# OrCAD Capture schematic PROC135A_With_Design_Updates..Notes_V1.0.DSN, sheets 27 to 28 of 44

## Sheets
27 27. XDS110 DEBUGGER: size C; title: XDS110 DEBUGGER
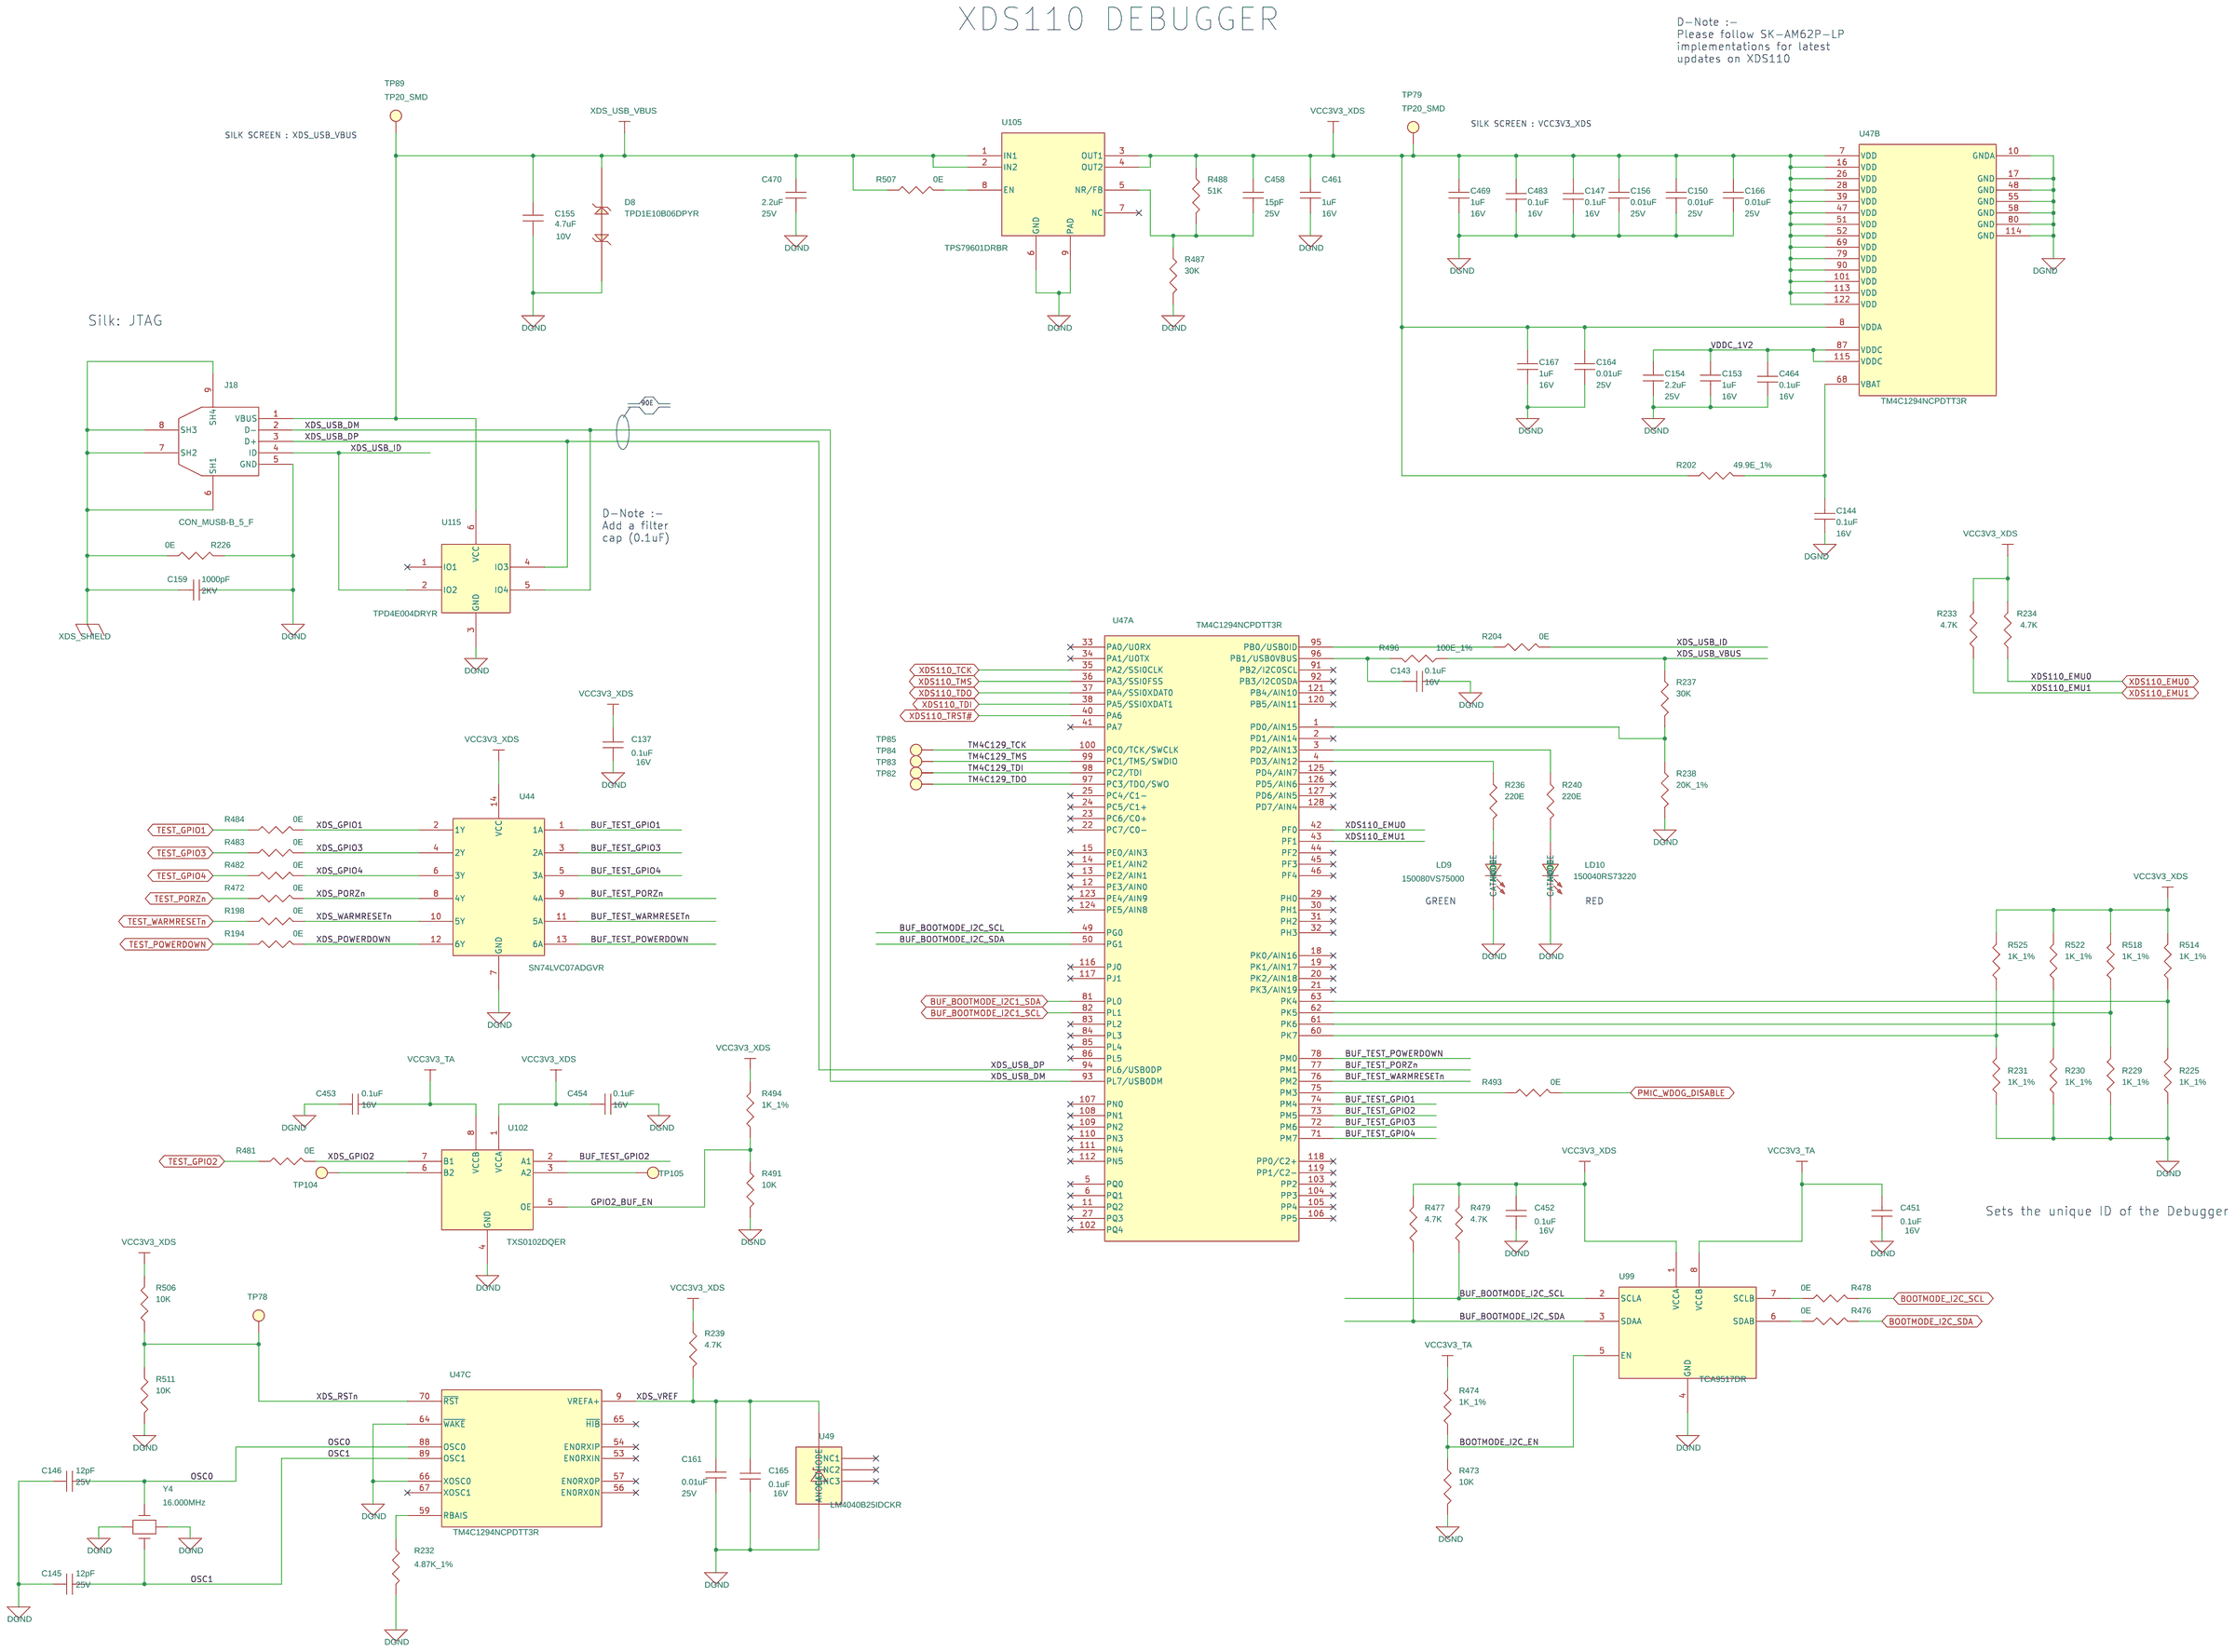
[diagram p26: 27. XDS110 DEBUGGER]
28 28. JTAG BUFFER: size C; title: JTAG BUFFER
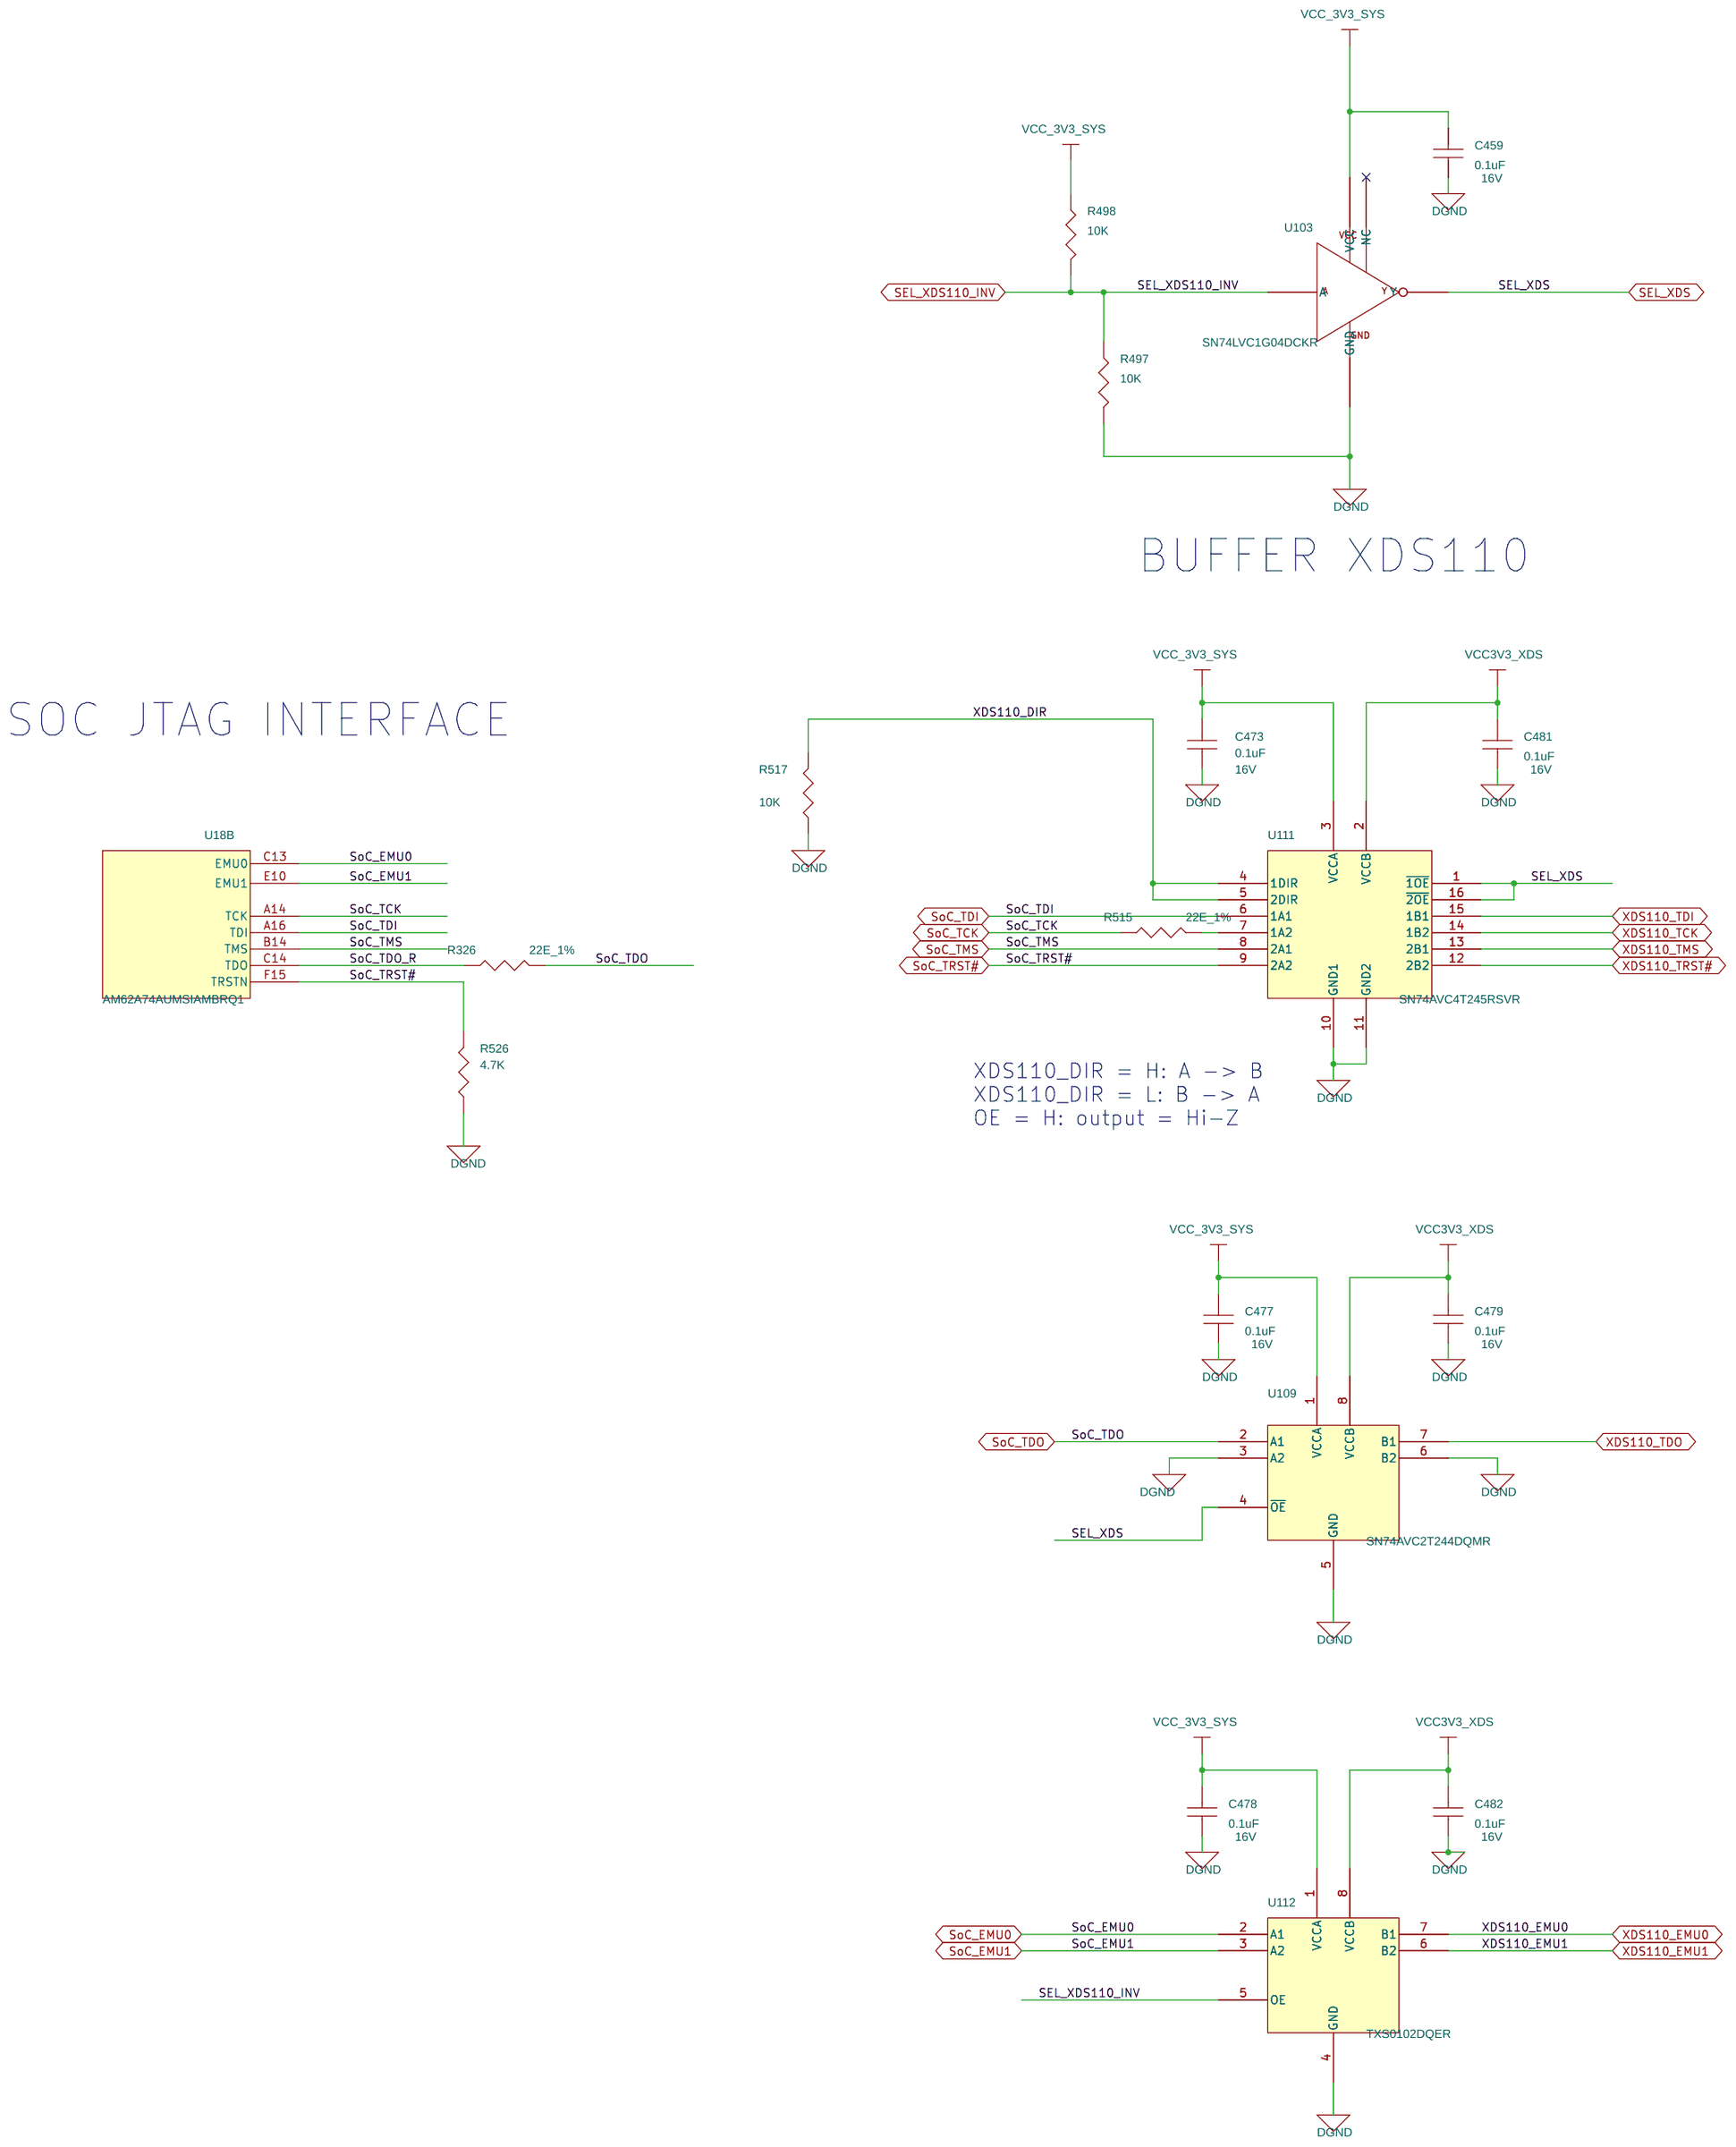
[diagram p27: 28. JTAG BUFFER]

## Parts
sheet 27. XDS110 DEBUGGER
C137  0.1uF  [CAP0201_0-5]
C143  0.1uF  [CAP0201_0-5]
C144  0.1uF  [CAP0201_0-5]
C145  12pF  [CAP0201_0-5]
C146  12pF  [CAP0201_0-5]
C147  0.1uF  [CAP0201_0-5]
C150  0.01uF  [CAP0201_0-5]
C153  1uF  [CAP0201_0-5]
C154  2.2uF  [CAP0402_0-75]
C155  4.7uF  [CAP0402_0-75]
C156  0.01uF  [CAP0201_0-5]
C159  1000pF  [CAP1206_1-75]
C161  0.01uF  [CAP0201_0-5]
C164  0.01uF  [CAP0201_0-5]
C165  0.1uF  [CAP0201_0-5]
C166  0.01uF  [CAP0201_0-5]
C167  1uF  [CAP0201_0-5]
C451  0.1uF  [CAP0201_0-5]
C452  0.1uF  [CAP0201_0-5]
C453  0.1uF  [CAP0201_0-5]
C454  0.1uF  [CAP0201_0-5]
C458  15pF  [CAP0201_0-5]
C461  1uF  [CAP0201_0-5]
C464  0.1uF  [CAP0201_0-5]
C469  1uF  [CAP0201_0-5]
C470  2.2uF  [CAP0402_0-75]
C483  0.1uF  [CAP0201_0-5]
D8  TPD1E10B06DPYR  [DIO_DFN0402_0-5]
J18  CON_MUSB-B_5_F  [CON_MUSBB5_629105150521_S_R_S_2-7]
LD9  150080VS75000  [LED_150080VS75000_80X50_SMD_0-8]
LD10  150040RS73220  [LED_150040GS73220_40X20_SMD_0-4]
R194  0E  [RES0201_0-5]
R198  0E  [RES0201_0-5]
R202  49.9E_1%  [RES0402_0-5]
R204  0E  [RES0201_0-5]
R225  1K_1%  [RES0402_0-5]
R226  0E  [RES0603_0-75]
R229  1K_1%  [RES0402_0-5]
R230  1K_1%  [RES0402_0-5]
R231  1K_1%  [RES0402_0-5]
R232  4.87K_1%  [RES0402_0-5]
R233  4.7K  [RES0201_0-5]
R234  4.7K  [RES0201_0-5]
R236  220E  [RES0402_0-5]
R237  30K  [RES0402_0-5]
R238  20K_1%  [RES0402_0-5]
R239  4.7K  [RES0201_0-5]
R240  220E  [RES0402_0-5]
R472  0E  [RES0201_0-5]
R473  10K  [RES0201_0-5]
R474  1K_1%  [RES0402_0-5]
R476  0E  [RES0201_0-5]
R477  4.7K  [RES0201_0-5]
R478  0E  [RES0201_0-5]
R479  4.7K  [RES0201_0-5]
R481  0E  [RES0201_0-5]
R482  0E  [RES0201_0-5]
R483  0E  [RES0201_0-5]
R484  0E  [RES0201_0-5]
R487  30K  [RES0402_0-5]
R488  51K  [RES0402_0-5]
R491  10K  [RES0201_0-5]
R493  0E  [RES0201_0-5]
R494  1K_1%  [RES0402_0-5]
R496  100E_1%  [RES0402_0-5]
R506  10K  [RES0201_0-5]
R507  0E  [RES0201_0-5]
R511  10K  [RES0201_0-5]
R514  1K_1%  [RES0402_0-5]
R518  1K_1%  [RES0402_0-5]
R522  1K_1%  [RES0402_0-5]
R525  1K_1%  [RES0402_0-5]
TP78  TP20_SMD  [TP20_SMD]
TP79  TP20_SMD  [TP20_SMD]
TP82  TP20_SMD  [TP20_SMD]
TP83  TP20_SMD  [TP20_SMD]
TP84  TP20_SMD  [TP20_SMD]
TP85  TP20_SMD  [TP20_SMD]
TP89  TP20_SMD  [TP20_SMD]
TP104  TP20_SMD  [TP20_SMD]
TP105  TP20_SMD  [TP20_SMD]
U44  SN74LVC07ADGVR  [TVSOP14_15-74_180X150_1-2]
U47  TM4C1294NCPDTT3R  [TQFP128_15-74_550X550_1-2]  (sections A,B,C)
U49  LM4040B25IDCKR  [SC70-5_1-1]
U99  TCA9517DR  [SOIC8_1-8]
U102  TXS0102DQER  [X2SON8_TXS0102_40X60_0-4]
U105  TPS79601DRBR  [SON8_25-59_130X130_1]
U115  TPD4E004DRYR  [SON6_19-68_40X60_PB_0-6]
Y4  16.000MHz  [XTAL4_XRCGB-FM_80X60_SMD_0-7]
sheet 28. JTAG BUFFER
C459  0.1uF  [CAP0201_0-5]
C473  0.1uF  [CAP0201_0-5]
C477  0.1uF  [CAP0201_0-5]
C478  0.1uF  [CAP0201_0-5]
C479  0.1uF  [CAP0201_0-5]
C481  0.1uF  [CAP0201_0-5]
C482  0.1uF  [CAP0201_0-5]
R326  22E_1%  [RES0201_0-5]
R497  10K  [RES0201_0-5]
R498  10K  [RES0201_0-5]
R515  22E_1%  [RES0201_0-5]
R517  10K  [RES0201_0-5]
R526  4.7K  [RES0201_0-5]
U103  SN74LVC1G04DCKR  [SC70-5]
U109  SN74AVC2T244DQMR  [X2SON8_15-74_70X50]
U111  SN74AVC4T245RSVR  [UQFN16_TMUX1574_70X100_0-6]
U112  TXS0102DQER  [X2SON8_TXS0102_40X60_0-4]
sheet 41. OSCILLATOR
U18  AM62A74AUMSIAMBRQ1  [FBGA484_31-49_710X710_2-7]  (sections A,B,C,D,E,F,G,H,I,J,K,L,M,N,O,P,Q)

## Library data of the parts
C137 C143 C144 C147 C165 C451-C454 C459 C464 C473 C477-C479 C481-C483 = CAP: CAP CERAMIC 0.1uF 16V 10% X5R 0201; Alt_Mfr_name: YAGEO AMERICA; Alt_Mfr_part_number: CC0402KRX5R8BB104; Chkd/date: MANIRAJA/230118; Crtd /date: MANIRAJA/230118; Custom_Duty: 15%; Customs_HS_Code: 85322990; Distributor_name: DIGIKEY; Distributor_part_number: 490-14305-1-ND; Footprint Path: Y:\MIS_DATABASE\Library\ALTIUM_TOOL\PCB_FOOTPRINTS\Altium_Footprint_Lib.PcbLib; Height: 0.33MM; Library Path: Y:\MIS_DATABASE\Library\ALTIUM_TOOL\SCHEMATICS_PARTS\MS_DISCRETE_Library.schlib; Mfr_name: MURATA; Mfr_part_number: GRM033R61C104KE14D; Mistral Part No: 120009030072-R; Package: 0201; Part_type: CAPACITORS\CERAMIC; Project: TI_MAXIE_CPB; RoHS: RoHS; Temperature: -55°C+85°C; Tolerance: 10%; Voltage: 16V; Wattage: NA; Weight: 0.33mg; Datasheet: Y:\MIS_DATABASE\DATASHEETS\CAPACITORS\GRM033R61C104KE14.PDF
C145 C146 = CAP: CAP CERAMIC 12pF 25V 5% C0G(NP0) 0201; Chkd/date: MANIRAJA/020620; Crtd /date: ALVY/300520; Custom_Duty: 15%; Customs_HS_Code: 85322990; Distributor_name: DIGIKEY; Distributor_part_number: 490-3144-1-ND; Footprint Path: Y:\MIS_DATABASE\Library\ALTIUM_TOOL\PCB_FOOTPRINTS\Altium_Footprint_Lib.PcbLib; Height: 0.33MM; Library Path: Y:\MIS_DATABASE\Library\ALTIUM_TOOL\SCHEMATICS_PARTS\MS_DISCRETE_Library.schlib; Mfr_name: MURATA; Mfr_part_number: GRM0335C1E120JA01D; Mistral Part No: 120009030213-R; Package: 0201; Part_type: CAPACITORS\CERAMIC; Project: QCS610_NANOSOM; RoHS: RoHS; Temperature: -55°C+125°C; Tolerance: 5%; Voltage: 25V; Wattage: NA; Weight: 0.33mg; Datasheet: Y:\MIS_DATABASE\DATASHEETS\CAPACITORS\GRM0335C1E120JA01.PDF
C150 C156 C161 C164 C166 = CAP: CAP CERAMIC 0.01uF 25V 10% X5R 0201; Chkd/date: MANIRAJA/230118; Crtd /date: MANIRAJA/230118; Custom_Duty: 15%; Customs_HS_Code: 85322990; Distributor_name: DIGIKEY; Distributor_part_number: GRM033R61E103KA12J-ND; Footprint Path: Y:\MIS_DATABASE\Library\ALTIUM_TOOL\PCB_FOOTPRINTS\Altium_Footprint_Lib.PcbLib; Height: 0.33MM; Library Path: Y:\MIS_DATABASE\Library\ALTIUM_TOOL\SCHEMATICS_PARTS\MS_DISCRETE_Library.schlib; Mfr_name: MURATA; Mfr_part_number: GRM033R61E103KA12J; Mistral Part No: 120018010007-R; Package: 0201; Part_type: CAPACITORS\CERAMIC; Project: TI_MAXIE_CPB; RoHS: RoHS; Temperature: -55°C+85°C; Tolerance: 10%; Voltage: 25V; Wattage: NA; Weight: 0.33mg; Datasheet: Y:\MIS_DATABASE\DATASHEETS\CAPACITORS\GRM033R61E103KA12.PDF
C153 C167 C461 C469 = CAP: CAP CERAMIC 1uF 16V 20% X5R 0201; Chkd/date: MANIRAJA/300520; Crtd /date: ALVY/260520; Custom_Duty: 15%; Customs_HS_Code: 85322990; Distributor_name: DIGIKEY; Distributor_part_number: 490-18654-1-ND; Footprint Path: Y:\MIS_DATABASE\Library\ALTIUM_TOOL\PCB_FOOTPRINTS\Altium_Footprint_Lib.PcbLib; Height: 0.39MM; Library Path: Y:\MIS_DATABASE\Library\ALTIUM_TOOL\SCHEMATICS_PARTS\MS_DISCRETE_Library.schlib; Mfr_name: MURATA; Mfr_part_number: GRM033R61C105ME15D; Mistral Part No: 120018090038-R; Package: 0201; Part_type: CAPACITORS\CERAMIC; Project: QCS610_NANOSOM; RoHS: RoHS; Temperature: -55°C+85°C; Tolerance: 20%; Voltage: 16V; Wattage: NA; Weight: 0.33mg; Datasheet: Y:\MIS_DATABASE\DATASHEETS\CAPACITORS\GRM033R61C105ME15.PDF
C154 C470 = CAP: CAP CERAMIC 2.2uF 25V 10% X5R 0402; Chkd/date: ALVY/010721; Crtd /date: MANIRAJA/010721; Custom_Duty: 15%; Customs_HS_Code: 85322990; Distributor_name: DIGIKEY; Distributor_part_number: 490-12703-1-ND; Footprint Path: Y:\MIS_DATABASE\Library\ALTIUM_TOOL\PCB_FOOTPRINTS\Altium_Footprint_Lib.PcbLib; Height: 0.70MM; Library Path: Y:\MIS_DATABASE\Library\ALTIUM_TOOL\SCHEMATICS_PARTS\MS_DISCRETE_Library.schlib; Mfr_name: MURATA; Mfr_part_number: GRM155R61E225KE11D; Mistral Part No: 120015120001-R; Package: 0402; Part_type: CAPACITORS\CERAMIC; Project: TI_AM263X_CC; RoHS: RoHS; Temperature: -55°C+85°C; Tolerance: 10%; Voltage: 25V; Wattage: NA; Weight: 1.5mg; Datasheet: Y:\MIS_DATABASE\DATASHEETS\CAPACITORS\GRM155R61E225KE11.PDF
C155 = CAP: CAP CERAMIC 4.7uF 10V 20% X5R 0402; Chkd/date: MANIRAJA/110718; Crtd /date: ALVY/110718; Custom_Duty: 15%; Customs_HS_Code: 85322990; Distributor_name: DIGIKEY; Distributor_part_number: 490-14306-1-ND; Footprint Path: Y:\MIS_DATABASE\Library\ALTIUM_TOOL\PCB_FOOTPRINTS\Altium_Footprint_Lib.PcbLib; Height: 0.65MM; Library Path: Y:\MIS_DATABASE\Library\ALTIUM_TOOL\SCHEMATICS_PARTS\MS_DISCRETE_Library.schlib; Mfr_name: MURATA; Mfr_part_number: GRM155R61A475MEAAD; Mistral Part No: 120012060002-R; Package: 0402; Part_type: CAPACITORS\CERAMIC; Project: TI_J7SVB_PCIE_ADD-ON-CARD; RoHS: RoHS; Temperature: -55°C+85°C; Tolerance: 20%; Voltage: 10V; Wattage: NA; Weight: 14mg; Datasheet: Y:\MIS_DATABASE\DATASHEETS\CAPACITORS\GRM155R61A475MEAAD.PDF
C159 = CAP: CAP CERAMIC 1000pF 2KV 10% X7R 1206; Chkd/date: SHREESHAIL/291106; Crtd /date: MAZHAR/281106; Custom_Duty: 15%; Customs_HS_Code: 85322990; Distributor_name: DIGIKEY; Distributor_part_number: 478-2956-1-ND; Footprint Path: Y:\MIS_DATABASE\Library\ALTIUM_TOOL\PCB_FOOTPRINTS\Altium_Footprint_Lib.PcbLib; Height: 1.52MM; Library Path: Y:\MIS_DATABASE\Library\ALTIUM_TOOL\SCHEMATICS_PARTS\MS_DISCRETE_Library.schlib; Mfr_name: AVX CORPORATION; Mfr_part_number: 1206GC102KAT1A; Mistral Part No: 120015080006-R; Package: 1206; Part_type: CAPACITORS\CERAMIC; Project: ADR1B; RoHS: RoHS; Temperature: -55°C+125°C; Tolerance: 10%; Voltage: 2KV; Wattage: NA; Weight: 16.2mg; Datasheet: Y:\MIS_DATABASE\DATASHEETS\CAPACITORS\AVX_HV-MLC.PDF
C458 = CAP: CAP CERAMIC 15pF 25V 2% HI-Q C0G(NP0) 0201; Chkd/date: VASANTHA/081216; Crtd /date: MANIRAJA/081216; Custom_Duty: 15%; Customs_HS_Code: 85322990; Distributor_name: DIGIKEY; Distributor_part_number: 490-10562-1-ND; Footprint Path: Y:\MIS_DATABASE\Library\ALTIUM_TOOL\PCB_FOOTPRINTS\Altium_Footprint_Lib.PcbLib; Height: 0.33MM; Library Path: Y:\MIS_DATABASE\Library\ALTIUM_TOOL\SCHEMATICS_PARTS\MS_DISCRETE_Library.schlib; Mfr_name: MURATA; Mfr_part_number: GJM0335C1E150GB01D; Mistral Part No: 120016120011-R; Package: 0201; Part_type: CAPACITORS\CERAMIC; Project: OCTBTS5200; RoHS: RoHS; Temperature: -55°C+125°C; Tolerance: 2%; Voltage: 25V; Wattage: NA; Weight: 0.33mg; Datasheet: Y:\MIS_DATABASE\DATASHEETS\CAPACITORS\MURATA-GXX-SER_NOV17.PDF
D8 = DIODE_SOD323: DIODE 1CH ESD PROTECTION X1SON2; Chkd/date: MANIRAJA/040420; Crtd /date: VASANTHA/181114; Custom_Duty: 15%; Customs_HS_Code: 85423100; Distributor_name: DIGIKEY; Distributor_part_number: 296-30406-1-ND; Footprint Path: Y:\MIS_DATABASE\Library\ALTIUM_TOOL\PCB_FOOTPRINTS\Altium_Footprint_Lib.PcbLib; Height: 0.45MM; Library Path: Y:\MIS_DATABASE\Library\ALTIUM_TOOL\SCHEMATICS_PARTS\MS_DISCRETE_Library.schlib; Mfr_name: TEXAS INSTRUMENTS; Mistral Part No: 130014110022-R; Package: X1SON2; Part_type: DIODE; Project: GALILEO_EVM; RoHS: RoHS; Temperature: -40°C+125°C; Tolerance: NA; Voltage: NA; Wattage: NA; Weight: 1mg; Datasheet: Y:\MIS_DATABASE\DATASHEETS\ICS\INTERFACE\TPD1E10B06-SER.PDF
J18 = CON_USB_MINI-B: CON MICRO USB TYPE B 5POS FEMALE RT SMD; Chkd/date: MANIRAJA/150519; Crtd /date: ALVY/150519; Custom_Duty: 24%; Customs_HS_Code: 85369090; Distributor_name: DIGIKEY; Distributor_part_number: 732-5960-1-ND; Footprint Path: Y:\MIS_DATABASE\Library\ALTIUM_TOOL\PCB_FOOTPRINTS\Altium_Footprint_Lib.PcbLib; Height: 2.66MM; Library Path: Y:\MIS_DATABASE\Library\ALTIUM_TOOL\SCHEMATICS_PARTS\MS_CONNECTOR_Library.schlib; Mfr_name: WURTH ELECTRONICS; Mfr_part_number: 629105150521; Mistral Part No: 150019050015-R; Package: SMD; Part_type: CONNECTOR\USB; Project: NEXTNAV_ALT-STATION_ATE_BRD; RoHS: RoHS; Temperature: -40°C+85°C; Tolerance: NA; Voltage: NA; Wattage: NA; Weight: 360mg; Datasheet: Y:\MIS_DATABASE\DATASHEETS\CONNECTORS\629105150521.PDF
LD9 = DIODE_LED: DIODE LED BRIGHT GREEN SMD; Chkd/date: MANIRAJA/180820; Crtd /date: ALVY/180820; Custom_Duty: 24%; Customs_HS_Code: 85439000; Distributor_name: DIGIKEY; Distributor_part_number: 732-4986-1-ND; Footprint Path: Y:\MIS_DATABASE\Library\ALTIUM_TOOL\PCB_FOOTPRINTS\Altium_Footprint_Lib.PcbLib; Height: 0.80MM; Library Path: Y:\MIS_DATABASE\Library\ALTIUM_TOOL\SCHEMATICS_PARTS\MS_OPTO_Library.schlib; Mfr_name: WURTH ELECTRONICS; Mistral Part No: 130020080012-R; Package: SMD; Part_type: OPTO\LED; Project: AM64x_EVM_BRD; RoHS: RoHS; Temperature: -40°C+85°C; Tolerance: NA; Voltage: NA; Wattage: NA; Weight: 10mg; Datasheet: Y:\MIS_DATABASE\DATASHEETS\DISCRETES\LEDS\150080VS75000.PDF
LD10 = DIODE_LED: DIODE LED RED SMD; Chkd/date: MANIRAJA/100920; Crtd /date: ALVY/100920; Custom_Duty: 24%; Customs_HS_Code: 85439000; Distributor_name: DIGIKEY; Distributor_part_number: 732-13422-1-ND; Footprint Path: Y:\MIS_DATABASE\Library\ALTIUM_TOOL\PCB_FOOTPRINTS\Altium_Footprint_Lib.PcbLib; Height: 0.35MM; Library Path: Y:\MIS_DATABASE\Library\ALTIUM_TOOL\SCHEMATICS_PARTS\MS_OPTO_Library.schlib; Mfr_name: WURTH ELECTRONICS; Mistral Part No: 130020090020-R; Package: SMD; Part_type: OPTO\LED; Project: AM64X_SKEVM; RoHS: RoHS; Temperature: -40°C+85°C; Tolerance: NA; Voltage: NA; Wattage: NA; Weight: 29.3mg; Datasheet: Y:\MIS_DATABASE\DATASHEETS\DISCRETES\LEDS\150040RS73220.PDF
R194 R198 R204 R472 R476 R478 R481-R484 R493 R507 = RESISTOR: RES 0E 1/20W 5% 0201; Chkd/date: NAVEED/301214; Crtd /date: MUDDU/120710; Custom_Duty: 15%; Customs_HS_Code: 85332119; Distributor_name: DIGIKEY; Distributor_part_number: 311-0.0NCT-ND; Footprint Path: Y:\MIS_DATABASE\Library\ALTIUM_TOOL\PCB_FOOTPRINTS\Altium_Footprint_Lib.PcbLib; Height: 0.26MM; Library Path: Y:\MIS_DATABASE\Library\ALTIUM_TOOL\SCHEMATICS_PARTS\MS_DISCRETE_Library.schlib; Mfr_name: YAGEO AMERICA; Mfr_part_number: RC0201JR-070RL; Mistral Part No: 110010070067-R; Package: 0201; Part_type: RESISTORS\FIXED; Project: PB_BUGBASE; RoHS: RoHS; Temperature: -55°C+125°C; Tolerance: 5%; Voltage: NA; Wattage: 1/20W; Weight: 0.17mg; Datasheet: Y:\MIS_DATABASE\DATASHEETS\RESISTORS\RCXXXXL-SER_MAR18.PDF
R202 = RESISTOR: RES 49.9E 1/16W 1% 0402; Chkd/date: MANIRAJA/210519; Crtd /date: MANIRAJA/210519; Custom_Duty: 15%; Customs_HS_Code: 85332119; Distributor_name: DIGIKEY; Distributor_part_number: 541-3967-1-ND; Footprint Path: Y:\MIS_DATABASE\Library\ALTIUM_TOOL\PCB_FOOTPRINTS\Altium_Footprint_Lib.PcbLib; Height: 0.35MM; Library Path: Y:\MIS_DATABASE\Library\ALTIUM_TOOL\SCHEMATICS_PARTS\MS_DISCRETE_Library.schlib; Mfr_name: VISHAY; Mfr_part_number: CRCW040249R9FKEDC; Mistral Part No: 110009030846-R; Package: 0402; Part_type: RESISTORS\FIXED; Project: RFSU_RFTJ_CARD; RoHS: RoHS; Temperature: -55°C+155°C; Tolerance: 1%; Voltage: NA; Wattage: 1/16W; Weight: 0.65mg; Datasheet: Y:\MIS_DATABASE\DATASHEETS\RESISTORS\CRCW_C-SER.PDF
R225 R229-R231 R474 R494 R514 R518 R522 R525 = RESISTOR: RES 1K 1/10W 1% 0402; Chkd/date: VASANTHA/281216; Crtd /date: MAZHAR/150506; Custom_Duty: 15%; Customs_HS_Code: 85332119; Distributor_name: DIGIKEY; Distributor_part_number: P1.00KLCT-ND; Footprint Path: Y:\MIS_DATABASE\Library\ALTIUM_TOOL\PCB_FOOTPRINTS\Altium_Footprint_Lib.PcbLib; Height: 0.40MM; Library Path: Y:\MIS_DATABASE\Library\ALTIUM_TOOL\SCHEMATICS_PARTS\MS_DISCRETE_Library.schlib; Mfr_name: PANASONIC-ECG; Mfr_part_number: ERJ-2RKF1001X; Mistral Part No: 110009030411-R; Package: 0402; Part_type: RESISTORS\FIXED; Project: VOCERA; RoHS: RoHS; Temperature: -55°C+155°C; Tolerance: 1%; Voltage: NA; Wattage: 1/10W; Weight: 0.8mg; Datasheet: Y:\MIS_DATABASE\DATASHEETS\RESISTORS\PAN-ERJSER_NOV17.PDF
R226 = RESISTOR: RES 0E 1/10W 5% 0603; Chkd/date: MANIRAJA/051217; Crtd /date: BAVISH/180211; Custom_Duty: 15%; Customs_HS_Code: 85332119; Distributor_name: DIGIKEY; Distributor_part_number: 311-0.0GRCT-ND; Footprint Path: Y:\MIS_DATABASE\Library\ALTIUM_TOOL\PCB_FOOTPRINTS\Altium_Footprint_Lib.PcbLib; Height: 0.55MM; Library Path: Y:\MIS_DATABASE\Library\ALTIUM_TOOL\SCHEMATICS_PARTS\MS_DISCRETE_Library.schlib; Manufacturer: YAGEO AMERICA; Mfr_name: PANASONIC-ECG; Mfr_part_number: RC0603JR-070RL; Mistral Part No: 110011020013-R; Package: 0603; Part_type: RESISTORS\FIXED; Project: KENNEL; RoHS: RoHS; Temperature: -55°C+155°C; Tolerance: 5%; Voltage: NA; Wattage: 1/10W; Weight: 2mg; Datasheet: Y:\MIS_DATABASE\DATASHEETS\RESISTORS\RCXXXXL-SER_MAR18.PDF
R232 = RESISTOR: RES 4.87K 1/10W 1% 0402; Chkd/date: MAZHAR/150709; Crtd /date: USMAN/150109; Custom_Duty: 15%; Customs_HS_Code: 85332119; Distributor_name: DIGIKEY; Distributor_part_number: P4.87KLCT-ND; Footprint Path: Y:\MIS_DATABASE\Library\ALTIUM_TOOL\PCB_FOOTPRINTS\Altium_Footprint_Lib.PcbLib; Height: 0.40MM; Library Path: Y:\MIS_DATABASE\Library\ALTIUM_TOOL\SCHEMATICS_PARTS\MS_DISCRETE_Library.schlib; Mfr_name: PANASONIC-ECG; Mfr_part_number: ERJ-2RKF4871X; Mistral Part No: 110009030803-R; Package: 0402; Part_type: RESISTORS\FIXED; Project: BSN-II; RoHS: RoHS; Temperature: -55°C+155°C; Tolerance: 1%; Voltage: NA; Wattage: 1/10W; Weight: 0.8mg; Datasheet: Y:\MIS_DATABASE\DATASHEETS\RESISTORS\PAN-ERJSER_NOV17.PDF
R233 R234 R239 R477 R479 R526 = RESISTOR: RES 4.7K 1/20W 5% 0201; Chkd/date: MANIRAJA/200921; Crtd /date: ALVY/200921; Custom_Duty: 15%; Customs_HS_Code: 85332119; Distributor_name: DIGIKEY; Distributor_part_number: 311-4.7KNCT-ND; Footprint Path: Y:\MIS_DATABASE\Library\ALTIUM_TOOL\PCB_FOOTPRINTS\Altium_Footprint_Lib.PcbLib; Height: 0.26MM; Library Path: Y:\MIS_DATABASE\Library\ALTIUM_TOOL\SCHEMATICS_PARTS\MS_DISCRETE_Library.schlib; Mfr_name: YAGEO AMERICA; Mfr_part_number: RC0201JR-074K7L; Mistral Part No: 110021090007-R; Package: 0201; Part_type: RESISTORS\FIXED; Project: TI_AM62x SKEVM_BRD; RoHS: RoHS; Temperature: -55°C+125°C; Tolerance: 5%; Voltage: NA; Wattage: 1/20W; Weight: 0.17mg; Datasheet: Y:\MIS_DATABASE\DATASHEETS\RESISTORS\RCXXXXL-SER_MAR18.PDF
R236 R240 = RESISTOR: RES 220E 1/10W 5% 0402; Chkd/date: VASANTHA/291216; Crtd /date: GEETHA/260406; Custom_Duty: 15%; Customs_HS_Code: 85332119; Distributor_name: DIGIKEY; Distributor_part_number: P220JCT-ND; Footprint Path: Y:\MIS_DATABASE\Library\ALTIUM_TOOL\PCB_FOOTPRINTS\Altium_Footprint_Lib.PcbLib; Height: 0.40MM; Library Path: Y:\MIS_DATABASE\Library\ALTIUM_TOOL\SCHEMATICS_PARTS\MS_DISCRETE_Library.schlib; Mfr_name: PANASONIC-ECG; Mfr_part_number: ERJ-2GEJ221X; Mistral Part No: 110009030506-R; Package: 0402; Part_type: RESISTORS\FIXED; Project: RED EYE; RoHS: RoHS; Temperature: -55°C+155°C; Tolerance: 5%; Voltage: NA; Wattage: 1/10W; Weight: 0.8mg; Datasheet: Y:\MIS_DATABASE\DATASHEETS\RESISTORS\PAN-ERJSER_NOV17.PDF
R237 R487 = RESISTOR: RES 30K 1/16W 5% 0402; Chkd/date: MANIRAJA/230817; Crtd /date: MANIRAJA/230817; Custom_Duty: 15%; Customs_HS_Code: 85332119; Distributor_name: DIGIKEY; Distributor_part_number: 541-30KJCT-ND; Footprint Path: Y:\MIS_DATABASE\Library\ALTIUM_TOOL\PCB_FOOTPRINTS\Altium_Footprint_Lib.PcbLib; Height: 0.40MM; Library Path: Y:\MIS_DATABASE\Library\ALTIUM_TOOL\SCHEMATICS_PARTS\MS_DISCRETE_Library.schlib; Mfr_name: VISHAY; Mfr_part_number: CRCW040230K0JNED; Mistral Part No: 110017080023-R; Package: 0402; Part_type: RESISTORS\FIXED; Project: TI_MAXIE_CPB; RoHS: RoHS; Temperature: -55°C+155°C; Tolerance: 5%; Voltage: NA; Wattage: 1/16W; Weight: 0.65mg; Datasheet: Y:\MIS_DATABASE\DATASHEETS\RESISTORS\CRCW0603.PDF
R238 = RESISTOR: RES 20K 1/16W 1% 0402; Chkd/date: MANIRAJA/021120; Crtd /date: MANIRAJA/021120; Custom_Duty: 15%; Customs_HS_Code: 85332119; Distributor_name: DIGIKEY; Distributor_part_number: 541-20.0KLCT-ND; Footprint Path: Y:\MIS_DATABASE\Library\ALTIUM_TOOL\PCB_FOOTPRINTS\Altium_Footprint_Lib.PcbLib; Height: 0.40MM; Library Path: Y:\MIS_DATABASE\Library\ALTIUM_TOOL\SCHEMATICS_PARTS\MS_DISCRETE_Library.schlib; Mfr_name: VISHAY; Mfr_part_number: CRCW040220K0FKED; Mistral Part No: 110009030486-R; Package: 0402; Part_type: RESISTORS\FIXED; Project: VAGG_SBC_BRD; RoHS: RoHS; Temperature: -55°C+155°C; Tolerance: 1%; Voltage: NA; Wattage: 1/16W; Weight: 0.65mg; Datasheet: Y:\MIS_DATABASE\DATASHEETS\RESISTORS\CRCW0603.PDF
R473 R491 R497 R498 R506 R511 R517 = RESISTOR: RES 10K 1/20W 5% 0201; Chkd/date: MANIRAJA/050517; Crtd /date: MANIRAJA/050517; Custom_Duty: 15%; Customs_HS_Code: 85332119; Distributor_name: DIGIKEY; Distributor_part_number: 311-10KNCT-ND; Footprint Path: Y:\MIS_DATABASE\Library\ALTIUM_TOOL\PCB_FOOTPRINTS\Altium_Footprint_Lib.PcbLib; Height: 0.26MM; Library Path: Y:\MIS_DATABASE\Library\ALTIUM_TOOL\SCHEMATICS_PARTS\MS_DISCRETE_Library.schlib; Mfr_name: YAGEO AMERICA; Mfr_part_number: RC0201JR-0710KL; Mistral Part No: 110010070051-R; Package: 0201; Part_type: RESISTORS\FIXED; Project: GOLDEN-I LITE; RoHS: RoHS; Temperature: -55°C+125°C; Tolerance: 5%; Voltage: NA; Wattage: 1/20W; Weight: 0.17mg; Datasheet: Y:\MIS_DATABASE\DATASHEETS\RESISTORS\RCXXXXL-SER_MAR18.PDF
R488 = RESISTOR: RES 51K 1/16W 5% 0402; Chkd/date: MANIRAJA/230817; Crtd /date: MANIRAJA/230817; Custom_Duty: 15%; Customs_HS_Code: 85332119; Distributor_name: DIGIKEY; Distributor_part_number: 541-51KJCT-ND; Footprint Path: Y:\MIS_DATABASE\Library\ALTIUM_TOOL\PCB_FOOTPRINTS\Altium_Footprint_Lib.PcbLib; Height: 0.40MM; Library Path: Y:\MIS_DATABASE\Library\ALTIUM_TOOL\SCHEMATICS_PARTS\MS_DISCRETE_Library.schlib; Mfr_name: VISHAY; Mfr_part_number: CRCW040251K0JNED; Mistral Part No: 110009030966-R; Package: 0402; Part_type: RESISTORS\FIXED; Project: TI_MAXIE_CPB; RoHS: RoHS; Temperature: -55°C+155°C; Tolerance: 5%; Voltage: NA; Wattage: 1/16W; Weight: 0.65mg; Datasheet: Y:\MIS_DATABASE\DATASHEETS\RESISTORS\CRCW0603.PDF
R496 = RESISTOR: RES 100E 1/16W 1% 0402; Chkd/date: MANIRAJA/060318; Crtd /date: NAVEED/220714; Custom_Duty: 15%; Customs_HS_Code: 85332119; Distributor_name: DIGIKEY; Distributor_part_number: 311-100LRCT-ND; Footprint Path: Y:\MIS_DATABASE\Library\ALTIUM_TOOL\PCB_FOOTPRINTS\Altium_Footprint_Lib.PcbLib; Height: 0.40MM; Library Path: Y:\MIS_DATABASE\Library\ALTIUM_TOOL\SCHEMATICS_PARTS\MS_DISCRETE_Library.schlib; Mfr_name: YAGEO AMERICA; Mfr_part_number: RC0402FR-07100RL; Mistral Part No: 110014070015-R; Package: 0402; Part_type: RESISTORS\FIXED; Project: DLRU; RoHS: RoHS; Temperature: -55°C+155°C; Tolerance: 1%; Voltage: NA; Wattage: 1/16W; Weight: 0.65mg; Datasheet: Y:\MIS_DATABASE\DATASHEETS\RESISTORS\RCXXXXL-SER_MAR18.PDF
TP78 TP82-TP85 TP104 TP105 = TESTPOINT: TESTPOINT CIR 20 SMD; Chkd/date: SHREESHAIL/171006; Crtd /date: MAZHAR/171006; Custom_Duty: NA; Customs_HS_Code: NA; Distributor_name: NA; Distributor_part_number: NA; Footprint Path: Y:\MIS_DATABASE\Library\ALTIUM_TOOL\PCB_FOOTPRINTS\Altium_Footprint_Lib.PcbLib; Height: NA; Library Path: Y:\MIS_DATABASE\Library\ALTIUM_TOOL\SCHEMATICS_PARTS\MS_DISCRETE_Library.schlib; MECHANICAL 3D STEP FILE: NA; Mfr_name: LOCAL; Mistral Part No: NA; Package: SMD; Project: BT MODULE_CSRBC04; RoHS: NA; Temperature: NA; Tolerance: NA; Voltage: NA; Wattage: NA; Weight: NA; Datasheet: NA
TP79 TP89 = TESTPOINT: TESTPOINT CIR 20 SMD; Chkd/date: SHREESHAIL/171006; Crtd /date: MAZHAR/171006; Custom_Duty: NA; Customs_HS_Code: NA; Distributor_name: NA; Distributor_part_number: NA; Footprint Path: Y:\MIS_DATABASE\Library\ALTIUM_TOOL\PCB_FOOTPRINTS\Altium_Footprint_Lib.PcbLib; Height: NA; Library Path: Y:\MIS_DATABASE\Library\ALTIUM_TOOL\SCHEMATICS_PARTS\MS_DISCRETE_Library.schlib; MECHANICAL 3D STEP FILE: NA; Manufacturer: LOCAL; Mfr_name: LOCAL; Mistral Part No: NA; Package: SMD; Project: BT MODULE_CSRBC04; RoHS: NA; Temperature: NA; Tolerance: NA; Voltage: NA; Wattage: NA; Weight: NA; Datasheet: NA
U44 = 74HC7014X_SOIC14: IC HEX BUFFER AND DRIVER WITH OPEN DRAIN OUTPUT TVSOP14; Chkd/date: ALVY/070422; Crtd /date: TAMILARASU/070422; Custom_Duty: 15%; Customs_HS_Code: 85423100; Distributor_name: DIGIKEY; Distributor_part_number: 296-8440-1-ND; Footprint Path: Y:\MIS_DATABASE\Library\ALTIUM_TOOL\PCB_FOOTPRINTS\Altium_Footprint_Lib.PcbLib; Height: 1.20MM; Library Path: Y:\MIS_DATABASE\Library\ALTIUM_TOOL\SCHEMATICS_PARTS\MS_COMBINATIONAL_Library.schlib; Mfr_name: TEXAS INSTRUMENTS; Mistral Part No: 141022040005-R; Package: TVSOP14; Part_type: ICS\DIGITAL\COMBINATIONAL; Project: TI_AM62x_SKEVM_BRD; RoHS: RoHS; Temperature: -40°C+125°C; Tolerance: NA; Voltage: NA; Wattage: NA; Weight: 41.8mg; Datasheet: Y:\MIS_DATABASE\DATASHEETS\ICS\DIGITAL\COMBINATIONAL\SN74LVC07A.PDF
U47 = TM4C1294NCPDTT3R_TQFP128: IC 32-BIT MICROCONTROLLER WITH 1MB FLASH TQFP128; Chkd/date: MANIRAJA/220817; Crtd /date: MANIRAJA/220817; Custom_Duty: 15%; Customs_HS_Code: 85423100; Distributor_name: DIGIKEY; Distributor_part_number: TM4C1294NCPDTT3R-ND; Height: 1.20MM; Mfr_name: TEXAS INSTRUMENTS; Mistral Part No: 141217080002-R; Package: TQF9128; Part_type: ICS\DIGITAL\MICROCONTROLLER; Project: TI_MAXIE_CPB; RoHS: RoHS; Temperature: -40°C+105°C; Tolerance: NA; Voltage: NA; Wattage: NA; Weight: 503.5mg; Datasheet: Y:\MIS_DATABASE\DATASHEETS\ICS\DIGITAL\MICROCONTROLLER\TM4C1294NCPD.PDF
U49 = LM4040B25IDCKR_SC70-5: IC PRECISION MICROPOWER SHUNT VOLTAGE REFERENCE SC70-5; Chkd/date: MANIRAJA/230817; Crtd /date: MANIRAJA/230817; Custom_Duty: 15%; Customs_HS_Code: 85423100; Distributor_name: DIGIKEY; Distributor_part_number: 296-20873-1-ND; Height: 1.10MM; Mfr_name: TEXAS INSTRUMENTS; Mistral Part No: 142017080015-R; Package: SC70-5; Part_type: ICS\POWER\VOLTAGE REGULATOR; Project: TI_MAXIE_CPB; RoHS: RoHS; Temperature: -40°C+85°C; Tolerance: NA; Voltage: NA; Wattage: NA; Weight: 30mg; Datasheet: Y:\MIS_DATABASE\DATASHEETS\ICS\POWER\LM4040B25I.PDF
U99 = TCA9517DGKR_VSSOP8: IC 2-CHANNEL BI-DIR LEVEL-SHIFTING I2C BUS REPEATER SOIC8; Chkd/date: MANIRAJA/171121; Crtd /date: ALVY/161121; Custom_Duty: 15%; Customs_HS_Code: 85423100; Distributor_name: DIGIKEY; Distributor_part_number: 296-39221-1-ND; Footprint Path: Y:\MIS_DATABASE\Library\ALTIUM_TOOL\PCB_FOOTPRINTS\Altium_Footprint_Lib.PcbLib; Height: 1.75MM; Library Path: Y:\MIS_DATABASE\Library\ALTIUM_TOOL\SCHEMATICS_PARTS\MS_MISCINTERFACE_Library.schlib; Mfr_name: TEXAS INSTRUMENTS; Mistral Part No: 141021110017-R; Package: SOIC8; Part_type: ICS\INTERFACE\LEVEL TRANSLATOR; Project: EXCITER MULTI-CH RX UNIT; RoHS: RoHS; Temperature: -40°C+85°C; Tolerance: NA; Voltage: NA; Wattage: NA; Weight: 540mg; Datasheet: Y:\MIS_DATABASE\DATASHEETS\ICS\INTERFACE\TCA9517.PDF
U102 U112 = TXS0102DQX_SON8: IC 2-BIT BI-DIR VOLTAGE-LEVEL TRANSLATOR FOR OPEN-DRAIN AND PUSH-PULL X2SON8; Chkd/date: MANIRAJA/010719; Crtd /date: CHAITHANYA230512; Custom_Duty: 15%; Customs_HS_Code: 85423100; Distributor_name: DIGIKEY; Distributor_part_number: 296-28368-1-ND; Footprint Path: Y:\MIS_DATABASE\Library\ALTIUM_TOOL\PCB_FOOTPRINTS\Altium_Footprint_Lib.PcbLib; Height: 0.40MM; Library Path: Y:\MIS_DATABASE\Library\ALTIUM_TOOL\SCHEMATICS_PARTS\MS_MISCINTERFACE_Library.schlib; Mfr_name: TEXAS INSTRUMENTS; Mistral Part No: 141012050010-R; Package: X2SON8; Part_type: ICS\INTERFACE\LEVEL TRANSLATOR; Project: GEN_3-8_DB; RoHS: RoHS; Temperature: -40°C+85°C; Tolerance: NA; Voltage: NA; Wattage: NA; Weight: 1.2mg; Datasheet: Y:\MIS_DATABASE\DATASHEETS\ICS\INTERFACE\TXS0102-SER.PDF
U105 = TPS79601DRBR_SON8: IC 1A HIGH PSRR RF ADJ LDO LINEAR REGULATOR SON8; Chkd/date: MANIRAJA/030518; Crtd /date: MAZHAR/280809; Custom_Duty: 15%; Customs_HS_Code: 85423100; Distributor_name: DIGIKEY; Distributor_part_number: 296-23107-1-ND; Footprint Path: Y:\MIS_DATABASE\Library\ALTIUM_TOOL\PCB_FOOTPRINTS\Altium_Footprint_Lib.PcbLib; Height: 1.00MM; Library Path: Y:\MIS_DATABASE\Library\ALTIUM_TOOL\SCHEMATICS_PARTS\MS_MISCPOWER_Library.schlib; Mfr_name: TEXAS INSTRUMENTS; Mistral Part No: 142009080012-R; Package: SON8; Part_type: ICS\POWER\VOLTAGE REGULATOR; Project: DIO_TXRX; RoHS: RoHS; Temperature: -40°C+125°C; Tolerance: NA; Voltage: NA; Wattage: NA; Weight: 24mg; Datasheet: Y:\MIS_DATABASE\DATASHEETS\MISC\REGULATORS\TPS796XX.PDF
U115 = TPD4E004_SON6: IC 4-CH ESD PROTECTION ARRAY FOR HIGH SPEED DATA INTERFACE SON6; Chkd/date: MANIRAJA/100320; Crtd /date: MUDDU/010310; Custom_Duty: 15%; Customs_HS_Code: 85423100; Distributor_name: DIGIKEY; Distributor_part_number: 296-23618-1-ND; Footprint Path: Y:\MIS_DATABASE\Library\ALTIUM_TOOL\PCB_FOOTPRINTS\Altium_Footprint_Lib.PcbLib; Height: 0.60MM; Library Path: Y:\MIS_DATABASE\Library\ALTIUM_TOOL\SCHEMATICS_PARTS\MS_MISCINTERFACE_Library.schlib; Mfr_name: TEXAS INSTRUMENTS; Mistral Part No: 141010020012-R; Package: SON6; Part_type: ICS\INTERFACE; Project: BUG_BASE-II; RoHS: RoHS; Temperature: -40°C+85°C; Tolerance: NA; Voltage: NA; Wattage: NA; Weight: 3.2mg; Datasheet: Y:\MIS_DATABASE\DATASHEETS\ICS\INTERFACE\TPD4E004-SER.PDF
Y4 = CRY4_13: CRY 16.000MHz 8pF SMD; Chkd/date: MANIRAJA/151020; Crtd /date: ALVY/151020; Custom_Duty: 24%; Customs_HS_Code: 85439000; Distributor_name: DIGIKEY; Distributor_part_number: 490-18283-1-ND; Footprint Path: Y:\MIS_DATABASE\Library\ALTIUM_TOOL\PCB_FOOTPRINTS\Altium_Footprint_Lib.PcbLib; Height: 0.70MM; Library Path: Y:\MIS_DATABASE\Library\ALTIUM_TOOL\SCHEMATICS_PARTS\MS_DISCRETE_Library.schlib; Mfr_name: MURATA; Mfr_part_number: XRCGB16M000FXN01R0; Mistral Part No: 130020100044-R; Package: SMD; Part_type: CRYSTAL; Project: AM64X_SKEVM; RoHS: RoHS; Temperature: -30°C+85°C; Tolerance: NA; Voltage: NA; Wattage: NA; Weight: 195.4mg; Datasheet: Y:\MIS_DATABASE\DATASHEETS\MISC\CRY_OSC\XRCGB16M000FXN01R0.PDF
R326 R515 = RESISTOR: RES 22E 1/20W 1% 0201; Chkd/date: MANIRAJA/080319; Crtd /date: ALVY/080319; Custom_Duty: 15%; Customs_HS_Code: 85332119; Distributor_name: DIGIKEY; Distributor_part_number: YAG2518CT-ND; Footprint Path: Y:\MIS_DATABASE\Library\ALTIUM_TOOL\PCB_FOOTPRINTS\Altium_Footprint_Lib.PcbLib; Height: 0.26MM; Library Path: Y:\MIS_DATABASE\Library\ALTIUM_TOOL\SCHEMATICS_PARTS\MS_DISCRETE_Library.schlib; Mfr_name: YAGEO AMERICA; Mfr_part_number: RC0201FR-0722RL; Mistral Part No: 110009030522-R; Package: 0201; Part_type: RESISTORS\FIXED; Project: AM654x_SOM; RoHS: RoHS; Temperature: -55°C+125°C; Tolerance: 1%; Voltage: NA; Wattage: 1/20W; Weight: 0.17mg; Datasheet: Y:\MIS_DATABASE\DATASHEETS\RESISTORS\RCXXXXL-SER_MAR18.PDF
U103 = SN74LVC1G04DCKR_SC70-5: IC SINGLE INVERTER GATE SC70-5; Chkd/date: SUHAS/221010; Crtd /date: USMAN/150709; Custom_Duty: 15%; Customs_HS_Code: 85423100; Distributor_name: DIGIKEY; Distributor_part_number: 296-11600-1-ND; Height: 1.10MM; Mfr_name: TEXAS INSTRUMENTS; Mistral Part No: 141009070007-R; Part_type: ICS\DIGITAL\GATES; Project: BUG_BASE-II; RoHS: Sb/ Br FREE; Temperature: -40°C+85°C; Datasheet: Y:\MIS_DATABASE\DATASHEETS\ICS\DIGITAL\GATES\SN74LVC1G04-1.PDF
U109 = SN74AVC2T244DQMR_X2SON8: IC 2-BIT UNDIRECTIONAL VOLTAGE-LEVEL TRANSLATOR X2SON8; Chkd/date: VASANTHA/060516; Crtd /date: VASANTHA/030316; Customs_HS_Code: 15%; Distributor_name: DIGIKEY; Distributor_part_number: 296-29674-1-ND; Height: 0.40MM; Mfr_name: TEXAS INSTRUMENTS; Mistral Part No: 141016030002-R; Package: X2SON8; Part_type: ICS\INTERFACE\LEVEL TRANSLATOR; Pb-Free: 85423100; Project: OCTASIC_3600; RoHS: RoHS; Temperature: -40°C+85°C; Tolerance: NA; Voltage: NA; Wattage: NA; Weight: NA; Datasheet: Y:\MIS_DATABASE\DATASHEETS\ICS\INTERFACE\SN74AVC2T244.PDF
U111 = SN74AVC4T245RSV_UQFN16: IC 2-BIT BUS TRANSCEIVER WITH CONFIGURABLE VOLTAGE TRANSLATION AND 3 STATE O/P UQFN16; Chkd/date: MANIRAJA/040520; Crtd /date: BAVISH/190411; Custom_Duty: 15%; Customs_HS_Code: 85423100; Distributor_name: DIGIKEY; Distributor_part_number: 296-24366-1-ND; Footprint Path: Y:\MIS_DATABASE\Library\ALTIUM_TOOL\PCB_FOOTPRINTS\Altium_Footprint_Lib.PcbLib; Height: 0.55MM; Library Path: Y:\MIS_DATABASE\Library\ALTIUM_TOOL\SCHEMATICS_PARTS\MS_BUSDRIVERTRANSCEIVER_Library.schlib; Mfr_name: TEXAS INSTRUMENTS; Mistral Part No: 141011040011-R; Package: UQFN16; Part_type: ICS\DIGITAL\BUSTRANSCEIVER; Project: HMC; RoHS: RoHS; Temperature: -40°C+85°C; Tolerance: NA; Voltage: NA; Wattage: NA; Weight: 41mg; Datasheet: Y:\MIS_DATABASE\DATASHEETS\ICS\DIGITAL\BUSTRANSCEIVER\SN74AVC4T245-SER.PDF
U18 = AM62A-EVM_SOC_FCBGA484: IC AM62A SK EVM SoC MICROPROCESSOR FCBGA484; Chkd/date: PRADEEP/020823; Crtd /date: PRADEEP/020823; Custom_Duty: 15%; Customs_HS_Code: 85423100; Distributor_name: NA; Distributor_part_number: NA; Footprint Path: Y:\MIS_DATABASE\Library\ALTIUM_TOOL\PCB_FOOTPRINTS\Altium_Footprint_Lib.PcbLib; Height: 2.65MM; Library Ref: AM62A-EVM_SoC_FCBGA484; Mfr_name: TEXAS INSTRUMENTS; Mistral Part No: 141230080001-R; Package: FCBGA484; Part_type: ICS\DIGITAL\MICROPROCESSOR; Project: TI_AM62A_SK_EVM; RoHS: NA; Temperature: NA; Tolerance: NA; Voltage: NA; Wattage: NA; Weight: NA; Datasheet: Y:\MIS_DATABASE\DATASHEETS\ICS\DIGITAL\MICROCONTROLLER\AM62A_SK_EVM.PDF

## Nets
DGND: C137.1 C143.1 C144.1 C145.1 C146.1 C147.1 C150.2 C153.2 C154.2 C155.2 C156.2 C159.1 C161.2 C164.2 C165.1 C166.2 C167.2 C451.1 C452.1 C453.1 C454.1 C459.1 C461.2 C464.1 C469.2 C470.2 C473.1 C477.1 C478.1 C479.1 C481.1 C482.1 C483.1 D8.1 J18.5(GND) LD9.1(CATHODE) LD10.1(CATHODE) R225.1 R226.1 R229.1 R230.1 R231.1 R232.2 R238.2 R473.1 R487.2 R491.1 R497.1 R511.2 R517.1 R526.2 U44.7(GND) U47.10(GNDA) U47.17(GND) U47.48(GND) U47.55(GND) U47.58(GND) U47.64(~{WAKE}) U47.66(XOSC0) U47.80(GND) U47.114(GND) U49.1(ANODE) U99.4(GND) U102.4(GND) U103.3(GND) U105.6(GND) U105.9(PAD) U109.3(A2) U109.5(GND) U109.6(B2) U111.10(GND1) U111.11(GND2) U112.4(GND) U115.3(GND) Y4.2 Y4.4 ; also on sheet 9 10 11 12 13 14 15 16 17 18 19 20 21 22 23 24 25 26 29 30 31 32 33 34 35 36 37 38 39 40 41 42 43
VCC3V3_TA: C451.2 C453.2 R474.2 U99.8(VCCB) U102.8(VCCB) ; also on sheet 25 26
VCC3V3_XDS: C137.2 C147.2 C150.1 C156.1 C164.1 C166.1 C167.1 C452.2 C454.2 C458.1 C461.1 C469.1 C479.2 C481.2 C482.2 C483.2 R202.2 R233.1 R234.1 R239.1 R477.1 R479.1 R488.1 R494.2 R506.2 R514.2 R518.2 R522.2 R525.2 TP79.1(TP) U44.14(VCC) U47.7(VDD) U47.8(VDDA) U47.16(VDD) U47.26(VDD) U47.28(VDD) U47.39(VDD) U47.47(VDD) U47.51(VDD) U47.52(VDD) U47.69(VDD) U47.79(VDD) U47.90(VDD) U47.101(VDD) U47.113(VDD) U47.122(VDD) U99.1(VCCA) U102.1(VCCA) U105.3(OUT1) U105.4(OUT2) U109.8(VCCB) U111.2(VCCB) U112.8(VCCB) ; also on sheet 25
VCC_3V3_SYS: C459.2 C473.2 C477.2 C478.2 R498.2 U103.5(VCC) U109.1(VCCA) U111.3(VCCA) U112.1(VCCA) ; also on sheet 9 10 12 13 17 18 19 21 22 23 25 26 29 30 32 33 34 35 36 37 38 39 40 41 42
VDDC_1V2: C153.1 C154.1 C464.2 U47.87(VDDC) U47.115(VDDC)
BOOTMODE_I2C_EN: R473.2 R474.1 U99.5(EN)
BOOTMODE_I2C_SCL: R478.1 ; also on sheet 25 26
BOOTMODE_I2C_SDA: R476.1 ; also on sheet 25 26
BUF_BOOTMODE_I2C1_SCL: U47.82(PL1) ; also on sheet 25
BUF_BOOTMODE_I2C1_SDA: U47.81(PL0) ; also on sheet 25
BUF_BOOTMODE_I2C_SCL: R479.2 U47.49(PG0) U99.2(SCLA)
BUF_BOOTMODE_I2C_SDA: R477.2 U47.50(PG1) U99.3(SDAA)
BUF_TEST_GPIO1: U44.1(1A) U47.74(PM4)
BUF_TEST_GPIO2: U47.73(PM5) U102.2(A1)
BUF_TEST_GPIO3: U44.3(2A) U47.72(PM6)
BUF_TEST_GPIO4: U44.5(3A) U47.71(PM7)
BUF_TEST_PORZn: U44.9(4A) U47.77(PM1)
BUF_TEST_POWERDOWN: U44.13(6A) U47.78(PM0)
BUF_TEST_WARMRESETn: U44.11(5A) U47.76(PM2)
GPIO2_BUF_EN: R491.2 R494.1 U102.5(OE)
OSC0: C146.2 U47.88(OSC0) Y4.3
OSC1: C145.2 U47.89(OSC1) Y4.1
PMIC_WDOG_DISABLE: R493.2 ; also on sheet 12
SEL_XDS: U103.4(Y) U109.4(~{OE}) U111.1(~{1OE}) U111.16(~{2OE}) ; also on sheet 29
SEL_XDS110_INV: R497.2 R498.1 U103.2(A) U112.5(OE) ; also on sheet 29
SoC_EMU0: U18.C13(EMU0) U112.2(A1) ; also on sheet 29
SoC_EMU1: U18.E10(EMU1) U112.3(A2) ; also on sheet 29
SoC_TCK: R515.1 U18.A14(TCK) ; also on sheet 29
SoC_TDI: U18.A16(TDI) U111.6(1A1) ; also on sheet 29
SoC_TDO: R326.1 U109.2(A1) ; also on sheet 29
SoC_TDO_R: R326.2 U18.C14(TDO)
SoC_TMS: U18.B14(TMS) U111.8(2A1) ; also on sheet 29
SoC_TRST#: R526.1 U18.F15(TRSTN) U111.9(2A2) ; also on sheet 29
TEST_GPIO1: R484.1 ; also on sheet 25 42
TEST_GPIO2: R481.1 ; also on sheet 25 39
TEST_GPIO3: R483.1 ; also on sheet 25 26
TEST_GPIO4: R482.1 ; also on sheet 25 26
TEST_PORZn: R472.1 ; also on sheet 25 41
TEST_POWERDOWN: R194.1 ; also on sheet 10 12 25
TEST_WARMRESETn: R198.1 ; also on sheet 25 42
TM4C129_TCK: TP85.1(TP) U47.100(PC0/TCK/SWCLK)
TM4C129_TDI: TP83.1(TP) U47.98(PC2/TDI)
TM4C129_TDO: TP82.1(TP) U47.97(PC3/TDO/SWO)
TM4C129_TMS: TP84.1(TP) U47.99(PC1/TMS/SWDIO)
XDS110_DIR: R517.2 U111.4(1DIR) U111.5(2DIR)
XDS110_EMU0: R234.2 U47.42(PF0) U112.7(B1)
XDS110_EMU1: R233.2 U47.43(PF1) U112.6(B2)
XDS110_TCK: U47.35(PA2/SSI0CLK) U111.14(1B2)
XDS110_TDI: U47.38(PA5/SSI0XDAT1) U111.15(1B1)
XDS110_TDO: U47.37(PA4/SSI0XDAT0) U109.7(B1)
XDS110_TMS: U47.36(PA3/SSI0FSS) U111.13(2B1)
XDS110_TRST#: U47.40(PA6) U111.12(2B2)
XDS_GPIO1: R484.2 U44.2(1Y)
XDS_GPIO2: R481.2 U102.7(B1)
XDS_GPIO3: R483.2 U44.4(2Y)
XDS_GPIO4: R482.2 U44.6(3Y)
XDS_PORZn: R472.2 U44.8(4Y)
XDS_POWERDOWN: R194.2 U44.12(6Y)
XDS_RSTn: R506.1 R511.1 TP78.1(TP) U47.70(~{RST})
XDS_SHIELD: C159.2 J18.6(SH1) J18.7(SH2) J18.8(SH3) J18.9(SH4) R226.2
XDS_USB_DM: J18.2(D-) U47.93(PL7/USB0DM) U115.5(IO4)
XDS_USB_DP: J18.3(D+) U47.94(PL6/USB0DP) U115.4(IO3)
XDS_USB_ID: J18.4(ID) R204.2 U115.2(IO2)
XDS_USB_VBUS: C155.1 C470.1 D8.2 J18.1(VBUS) R237.1 R496.1 R507.1 TP89.1(TP) U105.1(IN1) U105.2(IN2) U115.6(VCC)
XDS_VREF: C161.1 C165.2 R239.2 U47.9(VREFA+) U49.3(CATHODE)
XDS_WARMRESETn: R198.2 U44.10(5Y)
N16997746: R232.1 U47.59(RBAIS)
N17030208: R515.2 U111.7(1A2)
N17479799: R507.2 U105.8(EN)
N17479805: C458.2 R487.1 R488.2 U105.5(NR/FB)
N17479881: C144.2 R202.1 U47.68(VBAT)
N17481587: LD9.2(ANODE) R236.2
N17481598: C143.2 R496.2 U47.96(PB1/USB0VBUS)
N17481613: R204.1 U47.95(PB0/USB0ID)
N17481619: R237.2 R238.1 U47.1(PD0/AIN15)
N17481621: R231.2 R525.1 U47.60(PK7)
N17481627: R240.1 U47.3(PD2/AIN13)
N17481631: LD10.2(ANODE) R240.2
N17481633: R225.2 R514.1 U47.63(PK4)
N17481635: R230.2 R522.1 U47.61(PK6)
N17481637: R236.1 U47.4(PD3/AIN12)
N17481641: R229.2 R518.1 U47.62(PK5)
N22156088: R478.2 U99.7(SCLB)
N22156090: R476.2 U99.6(SDAB)
N23161423: R493.1 U47.75(PM3)
N23178593: TP104.1(TP) U102.6(B2)
N23178631: TP105.1(TP) U102.3(A2)

Not connected (* = marked no-connect by the designer): U47 2(PD1/AIN14)* 5(PQ0)* 6(PQ1)* 11(PQ2)* 12(PE3/AIN0)* 13(PE2/AIN1)* 14(PE1/AIN2)* 15(PE0/AIN3)* 18(PK0/AIN16)* 19(PK1/AIN17)* 20(PK2/AIN18)* 21(PK3/AIN19)* 22(PC7/C0-)* 23(PC6/C0+)* 24(PC5/C1+)* 25(PC4/C1-)* 27(PQ3)* 29(PH0)* 30(PH1)* 31(PH2)* 32(PH3)* 33(PA0/U0RX)* 34(PA1/U0TX)* 41(PA7)* 44(PF2)* 45(PF3)* 46(PF4)* 53(EN0RXIN)* 54(EN0RXIP)* 56(EN0RX0N)* 57(EN0RX0P)* 65(~{HIB})* 67(XOSC1)* 83(PL2)* 84(PL3)* 85(PL4)* 86(PL5)* 91(PB2/I2C0SCL)* 92(PB3/I2C0SDA)* 102(PQ4)* 103(PP2)* 104(PP3)* 105(PP4)* 106(PP5)* 107(PN0)* 108(PN1)* 109(PN2)* 110(PN3)* 111(PN4)* 112(PN5)* 116(PJ0)* 117(PJ1)* 118(PP0/C2+)* 119(PP1/C2-)* 120(PB5/AIN11)* 121(PB4/AIN10)* 123(PE4/AIN9)* 124(PE5/AIN8)* 125(PD4/AIN7)* 126(PD5/AIN6)* 127(PD6/AIN5)* 128(PD7/AIN4)*; U49 2(NC1)* 4(NC2)* 5(NC3)*; U103 1(NC)*; U105 7(NC)*; U115 1(IO1)*

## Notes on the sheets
sheet 27
- XDS110 DEBUGGER
- D-Note :-
  Please follow SK-AM62P-LP
  implementations for latest
  updates on XDS110
- SILK SCREEN : XDS_USB_VBUS
- SILK SCREEN : VCC3V3_XDS
- Silk: JTAG
- 90E
- D-Note :-
  Add a filter
  cap (0.1uF)
- GREEN
- RED
- Sets the unique ID of the Debugger
sheet 28
- BUFFER XDS110
- SOC JTAG INTERFACE
- XDS110_DIR = H: A -> B
  XDS110_DIR = L: B -> A
  OE = H: output = Hi-Z
